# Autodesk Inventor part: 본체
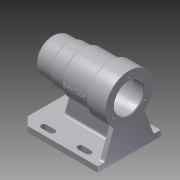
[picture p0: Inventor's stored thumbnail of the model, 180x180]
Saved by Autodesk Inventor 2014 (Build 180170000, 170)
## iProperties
Created: 2017-09
Part Number: 본체
Material: 알루미늄 6061
Document SubType Name: Modeling
Designer: user
Density: 2.71 g/cm^3
Appearance: 알루미늄 - 평지
Mass: 694.758 g
Surface Area: 712.421 cm^2
Volume: 256.368 cm^3
Author: user
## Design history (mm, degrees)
sketch "스케치1"
  geometry: L1 (0, 56)-(0, -56); L2 (21, -56)-(21, -41); L3 (21, -41)-(24, -41); L4 (24, -41)-(24, 13); L5 (24, 13)-(21, 13); L6 (21, 13)-(21, 25); L7 (21, 25)-(17.5, 25); L8 (17.5, 25)-(17.5, 43); L9 (17.5, 43)-(16, 43); L10 (16, 43)-(16, 47); L11 (16, 47)-(10.5, 47); L12 (10.5, 47)-(10.5, 50); L13 (25, 56)-(25, 31); L14 (25, 31)-(27, 31); L15 (27, 31)-(27, 11); L16 (27, 11)-(30, 11); L17 (30, 11)-(30, -28); L18 (30, -28)-(34, -28); L19 (34, -28)-(34, -56); L20 (34, -56)-(21, -56); L21 (25, 56)-(0, 56); L22 (10.5, 50)-(0, 50); L23 (0, 56)-(0, 50); 2 further points
  constraints: 46 end point, 6 perpendicular, 4 parallel, 2 point on line, 1 coincident, 1 collinear, 1 horizontal alignment, 1 midpoint, 1 vertical
  dimensions: "d0" = 112 distance of L1.start L1.end; "d1" = 42 diameter of L2 L1; "d2" = 48 diameter of L4 L1; "d3" = 15 distance of L2.start L2.end; "d4" = 54 distance of L3.end L4.end; "d5" = 42 diameter of L6 L1; "d6" = 12 distance of L5.end L6.end; "d7" = 18 distance of L7.end L8.end; "d8" = 35 diameter of L8 L1; "d9" = 32 diameter of L10 L1; "d11" = 4 distance of L9.end L10.end; "d13" = 3 distance of L11.end L12.end; "d14" = 21 diameter of L12 L1; "d20" = 60 diameter of L17 L1; "d21" = 54 diameter of L15 L1; "d22" = 50 diameter of L13 L1; "d23" = 68 diameter of L19 L1; "d24" = 112 distance between parallel lines of L20 L21; "d25" = 25 distance of L13.start L13.end; "d26" = 6 distance between parallel lines of L21 L22; "d28" = 3 distance of L2.end L3.end; "d29" = 3.5 distance of L6.end L7.end; "d30" = 1.5 distance of L8.end L9.end; "d32" = 45 distance from line of L15.end L21; "d33" = 84 distance between parallel lines of L18 L21
revolve "회전1" sketch "스케치1" stored, may be unused: angle "d27" = 90 deg
fillet "모깎기1" dims "d34" = 9
node "작업 평면1"
sketch "스케치2"
  geometry: L1 (-45, 56)-(45, 56); L2 (45, 56)-(45, -56); L3 (45, -56)-(-45, -56); L4 (-45, -56)-(-45, 56); L5 (-45, 56)-(45, -56); L6 (45, 56)-(-45, -56); 1 further point
  constraints: 12 end point, 2 midpoint, 2 parallel, 1 horizontal, 1 perpendicular
  dimensions: "d36" = 112 distance of L1.end L2.end; "d37" = 90 distance of L2.end L3.end
extrude "돌출1" join sketch "스케치2" distance "d38" = 8; taper "d39" = 0 deg
sketch "스케치3"
  geometry: C1 r 34 at (0, 0) reference; C2 r 21 at (0, 0) reference; A1 r 26 centre (0, 0) between (26, 0) and (-13, 22.517); 1 further point
  constraints: 3 point on circle, 1 centre point, 1 coincident, 1 horizontal alignment
  dimensions: "d40" = 52 diameter of A1; "d41" = 120 deg dimension on C1.centre A1.end A1.start; "d42" = 120 deg dimension on C1.centre point (-13, -22.517) A1.start
hole "구멍1" sketch "스케치3" at (26, 0), (-13, 22.517), (-13, -22.517) diameter "d43" = 3.242; stored, may be unused: countersink angle "d47" = 90 deg, drill point angle "d49" = 118 deg; dims "d44" = 8, "d45" = 4, "d46" = 2, "d48" = 11
sketch "스케치4"
  geometry: L1 (56, -45)-(56, 45) reference; L2 (56, 45)-(-56, 45) reference; L3 (-32, -34)-(-20, -34); L4 (-32, -38)-(-20, -38); L5 (-20, -30)-(-32, -30); L6 (20, -34)-(32, -34); L7 (20, -38)-(32, -38); L8 (32, -30)-(20, -30); L9 (-32, 34)-(-20, 34); L10 (-32, 30)-(-20, 30); L11 (-20, 38)-(-32, 38); L12 (20, 34)-(32, 34); L13 (20, 30)-(32, 30); L14 (32, 38)-(20, 38); A1 r 4 centre (-32, -34) between (-32, -30) and (-32, -38); A2 r 4 centre (-20, -34) between (-20, -38) and (-20, -30); A3 r 4 centre (20, -34) between (20, -30) and (20, -38); A4 r 4 centre (32, -34) between (32, -38) and (32, -30); A5 r 4 centre (-32, 34) between (-32, 38) and (-32, 30); A6 r 4 centre (-20, 34) between (-20, 30) and (-20, 38); A7 r 4 centre (20, 34) between (20, 38) and (20, 30); A8 r 4 centre (32, 34) between (32, 30) and (32, 38); 5 further points
  constraints: 32 end point, 16 point on circle, 16 tangent, 8 centre point, 8 parallel, 4 midpoint, 3 equal length, 1 horizontal alignment, 1 vertical alignment
  dimensions: "d50" = 34 vertical distance of point (0, 0) point (-26, 34); "d51" = 34 vertical distance of point (0, 0) point (-26, -34); "d52" = 4 radius of A5; "d53" = 4 radius of A8; "d54" = 4 radius of A4; "d55" = 4 radius of A2; "d56" = 12 distance of L9.end L9.start; "d57" = 40 distance of L12.start L9.end; "d58" = 40 distance of L6.start L3.end; "d59" = 24 distance from line of L1 L6.end; "d60" = 34 vertical distance of point (0, 0) point (26, 34)
extrude "돌출2" cut sketch "스케치4" stored distance "d61" = 8; taper "d62" = 0 deg
node "작업 평면2"
chamfer "모따기1" distance "d76" = 12; stored, may be unused: second distance "d77" = 2, angle "d78" = 45 deg
fillet "모깎기2" dims "d79" = 0.3
fillet "모깎기3" dims "d80" = 3
fillet "모깎기4" dims "d81" = 3
fillet "모깎기5" dims "d82" = 3
sketch "스케치7"
  geometry: L1 (-62, -56)-(-62, 44) reference; L2 (-27, 28.172)-(-27, 13.196) reference; L3 (-27, 24.622)-(-62, 34); L4 (-70, 56)-(-62, 56) reference; L5 (-62, 34)-(-62, -56); L6 (-34.002, -56)-(-62, -56); L7 (-34, -31)-(-34, -56) reference; 1 further point
  constraints: 6 end point, 2 perpendicular, 2 point on line
  dimensions: "d83" = 105 deg angle of L1 L3; "d84" = 22 distance from line of L4 L3.end; "d86" = 27.99839 distance of L6.start L1.start
feature "리브1" sketch "스케치7" dims "d87" = 1, "d88" = 8, "d89" = 0, "d90" = 0, "d91" = 1, "d92" = 1
sketch "스케치8"
  geometry: L1 (8, 41)-(8, 0) reference; L2 (8, 41)-(36.236, 41) reference; L3 (36.236, 49)-(8, 49) reference; L4 (8, 90)-(8, 49) reference; L5 (43.992, 66.9)-(8, 80); L6 (43.992, 23.1)-(8, 10); A1 r 34 centre (70, 45) between (36.236, 41) and (36.236, 49) reference
  constraints: 4 end point, 2 point on circle, 2 point on line, 1 equal length
  dimensions: "d93" = 110 deg angle of L5 L4; "d94" = 10 distance of L4.start L5.end; "d95" = 110 deg angle of L1 L6
extrude "돌출5" join sketch "스케치8" distance "d96" = 8; taper "d97" = 0 deg
fillet "모깎기6" dims "d98" = 3
fillet "모깎기7" dims "d99" = 3
chamfer "모따기2" distance "d100" = 1; stored, may be unused: second distance "d101" = 2, angle "d102" = 45 deg
node "작업 평면3"
sketch "스케치9"
  geometry: L1 (-26.008, -56)-(34, -56) reference; L2 (-70, 44)-(-70, -56) reference; 2 further points
  constraints: 1 other
  dimensions: "d104" = 48 distance from line of L1 point (0, -8); "d105" = 70 distance from line of L2 point (0, -8)
feature "엠보싱1" sketch "스케치9" dims "d106" = 0.5, "d107" = 0
node "솔리드1"
other parameters: "d103" = 35
